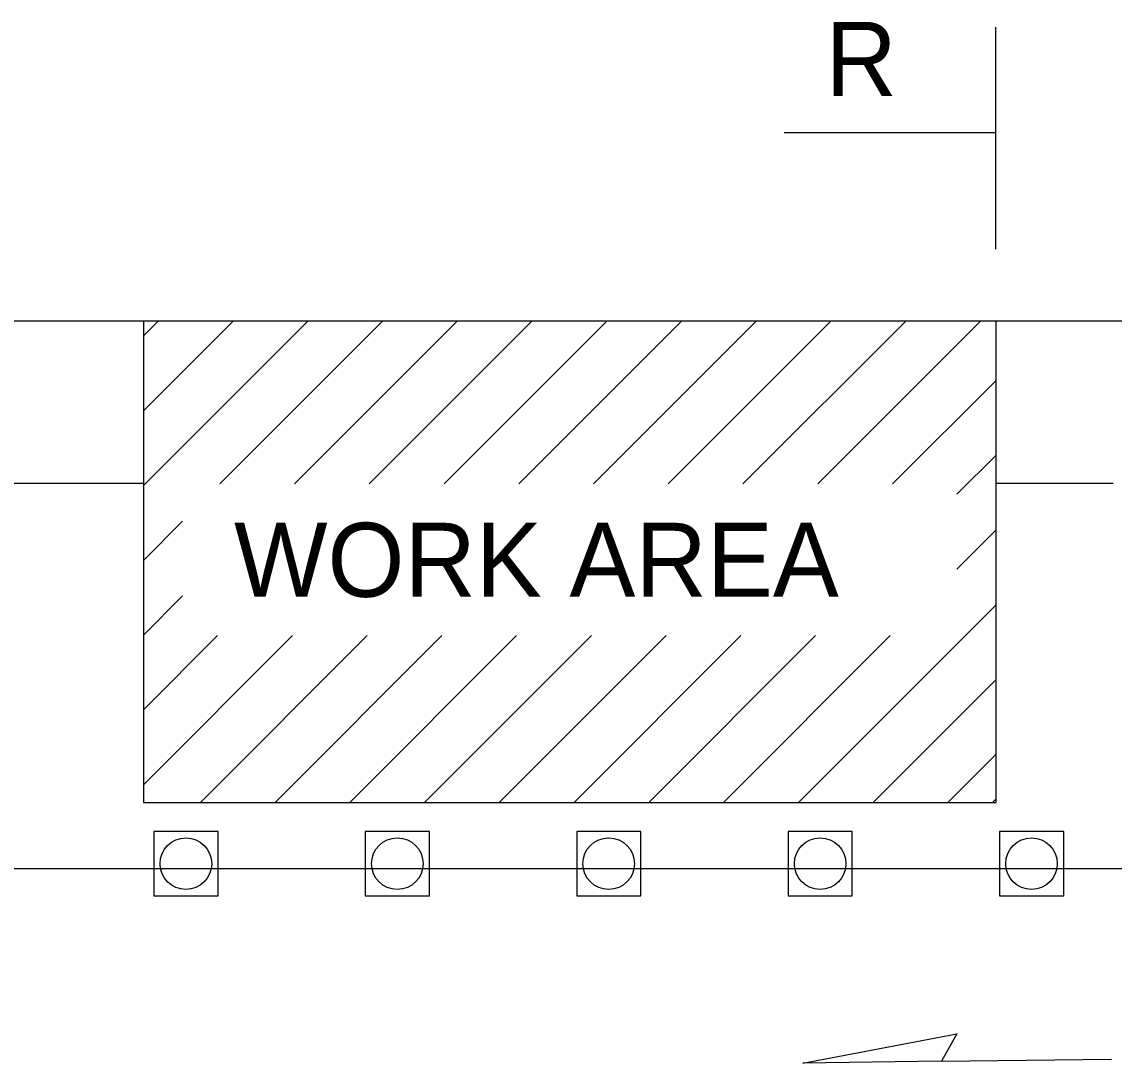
# Model space of a CAD drawing. Extents: x 99988 to 100172, y 99995 to 100047.
# Drawn here: x 100007.282 to 100008.315, y 100005.313 to 100006.297 of the extents above; entities that cross this region are included whole.
import ezdxf

# ---------------------------------------------------------------- set-up
doc = ezdxf.new("R2010")
doc.units = 0
for name, color, linetype in [('Default', 7, 'Continuous'), ('SH_DE_DetailBody1Text', 7, 'Continuous'), ('SH_GI_TrafficMvmntArrowRt1Lane', 7, 'Continuous'), ('SH_RS_ConstructionNoteFlag', 7, 'Continuous'), ('SH_RS_DimensionLines', 7, 'Continuous'), ('TR_WZ_TrafficSafetyCone', 7, 'Continuous'), ('TR_WZ_WorkZoneDetails', 7, 'Continuous')]:
    doc.layers.add(name, color=color, linetype=linetype)

msp = doc.modelspace()

# ---------------------------------------------------------------- linework, layer by layer
at = {"layer": 'Default'}
msp.add_line((100011.7483, 100005.4964), (100005.4457, 100005.4964), dxfattribs=at)
at = {"layer": 'SH_GI_TrafficMvmntArrowRt1Lane'}
msp.add_line((100008.152, 100005.3145), (100008.3128, 100005.3166), dxfattribs=at)
msp.add_lwpolyline([(100008.021, 100005.3127), (100008.1666, 100005.3404), (100008.152, 100005.3145)], close=True, dxfattribs=at)
at = {"layer": 'SH_RS_DimensionLines'}
msp.add_line((100008.2034, 100006.1922), (100008.0034, 100006.1922), dxfattribs=at)
at = {"layer": 'TR_WZ_TrafficSafetyCone'}
for points in [[(100007.407, 100005.4709), (100007.4677, 100005.4709), (100007.4677, 100005.5316), (100007.407, 100005.5316)], [(100007.607, 100005.4709), (100007.6677, 100005.4709), (100007.6677, 100005.5316), (100007.607, 100005.5316)], [(100007.807, 100005.4709), (100007.8677, 100005.4709), (100007.8677, 100005.5316), (100007.807, 100005.5316)], [(100008.007, 100005.4709), (100008.0677, 100005.4709), (100008.0677, 100005.5316), (100008.007, 100005.5316)], [(100008.207, 100005.4709), (100008.2677, 100005.4709), (100008.2677, 100005.5316), (100008.207, 100005.5316)]]:
    msp.add_lwpolyline(points, close=True, dxfattribs=at)
for centre in [(100007.4373, 100005.5013), (100007.6373, 100005.5013), (100007.8373, 100005.5013), (100008.0373, 100005.5013), (100008.2373, 100005.5013)]:
    msp.add_circle(centre, 0.0244, dxfattribs=at)
at = {"layer": 'TR_WZ_WorkZoneDetails'}
for p, q in [((100008.2034, 100006.0823), (100008.2034, 100006.2922)), ((100007.3972, 100006.0142), (100002.4293, 100006.0142)), ((100007.3972, 100006.0003), (100007.4112, 100006.0142)), ((100007.3972, 100005.9296), (100007.4819, 100006.0142)), ((100007.3972, 100005.8589), (100007.5526, 100006.0142)), ((100007.4694, 100005.8603), (100007.6233, 100006.0142)), ((100007.5401, 100005.8603), (100007.694, 100006.0142)), ((100007.6108, 100005.8603), (100007.7647, 100006.0142)), ((100007.6815, 100005.8603), (100007.8354, 100006.0142)), ((100007.7522, 100005.8603), (100007.9061, 100006.0142)), ((100007.8229, 100005.8603), (100007.9768, 100006.0142)), ((100007.8936, 100005.8603), (100008.0475, 100006.0142)), ((100007.9643, 100005.8603), (100008.1183, 100006.0142)), ((100008.035, 100005.8603), (100008.189, 100006.0142)), ((100011.7483, 100006.0142), (100008.2037, 100006.0142)), ((100008.1058, 100005.8603), (100008.2037, 100005.9582)), ((100008.1667, 100005.8506), (100008.2037, 100005.8875)), ((100007.3972, 100005.8608), (100002.4254, 100005.8608)), ((100008.3144, 100005.8608), (100008.2037, 100005.8608)), ((100007.3972, 100005.7881), (100007.4341, 100005.8251)), ((100008.1667, 100005.7799), (100008.2037, 100005.8168)), ((100007.3972, 100005.7174), (100007.4341, 100005.7544)), ((100008.0167, 100005.5591), (100008.2037, 100005.7461)), ((100007.3972, 100005.6467), (100007.4673, 100005.7169)), ((100007.3972, 100005.576), (100007.538, 100005.7169)), ((100007.451, 100005.5591), (100007.6087, 100005.7169)), ((100007.5217, 100005.5591), (100007.6795, 100005.7169)), ((100007.5924, 100005.5591), (100007.7502, 100005.7169)), ((100007.6631, 100005.5591), (100007.8209, 100005.7169)), ((100007.7338, 100005.5591), (100007.8916, 100005.7169)), ((100007.8046, 100005.5591), (100007.9623, 100005.7169)), ((100007.8753, 100005.5591), (100008.033, 100005.7169)), ((100007.946, 100005.5591), (100008.1037, 100005.7169)), ((100008.0874, 100005.5591), (100008.2037, 100005.6754)), ((100008.1581, 100005.5591), (100008.2037, 100005.6047)), ((100008.2003, 100005.5591), (100008.2037, 100005.5625))]:
    msp.add_line(p, q, dxfattribs=at)
msp.add_lwpolyline([(100007.3972, 100005.5591), (100008.2037, 100005.5591), (100008.2037, 100006.0142), (100007.3972, 100006.0142)], close=True, dxfattribs=at)

# ---------------------------------------------------------------- texts
at = {"layer": 'SH_DE_DetailBody1Text'}
msp.add_text('WORK AREA', height=0.07, dxfattribs=at).set_placement((100007.4829, 100005.7536))
at = {"layer": 'SH_RS_ConstructionNoteFlag'}
msp.add_text('R', height=0.07, dxfattribs=at).set_placement((100008.0423, 100006.2272))

doc.saveas('drawing.dxf')
